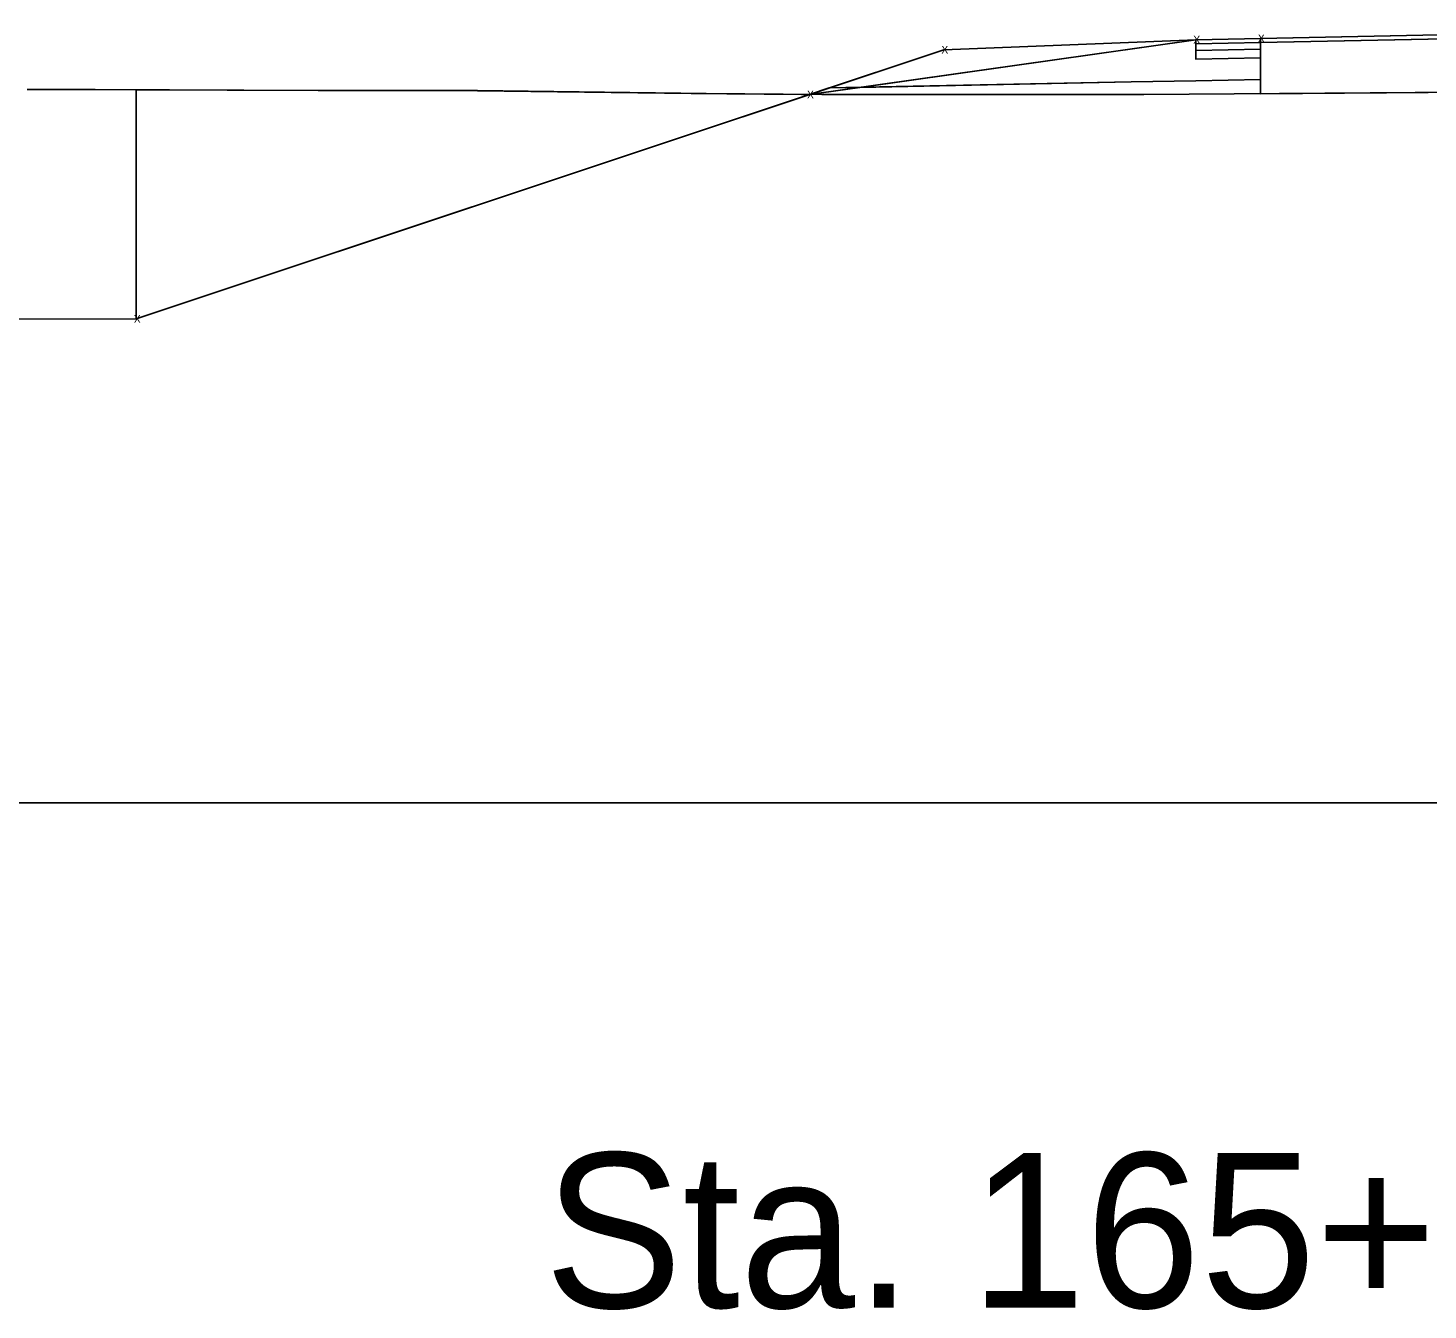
# Model space of a CAD drawing. Extents: x -26 to 303, y -16 to 6048.
# Drawn here: x 95.72 to 139.11, y 3984.28 to 4024.02 of the extents above; entities that cross this region are included whole.
import ezdxf

# ---------------------------------------------------------------- set-up
doc = ezdxf.new("R2010")
doc.units = 0
for name, color, linetype in [('ASPHALT_19MM1', 7, 'Continuous'), ('ASPHALT_9_5MM1', 7, 'Continuous'), ('CONST_DCH', 7, 'Continuous'), ('CONST_LV3', 7, 'Continuous'), ('Draft_XS_Text', 7, 'Continuous'), ('DTM_P_FINISHED_GRADE2', 7, 'Continuous'), ('DTM_TEMP_DROP', 7, 'Continuous'), ('DTM_X_GROUND', 7, 'Continuous'), ('TRANS_PAVED_SHOULDERS', 7, 'Continuous'), ('X_PROFILES_1', 7, 'Continuous'), ('XS_CELL', 7, 'Continuous'), ('XS_M_SHAPES_EARTHWORK', 7, 'Continuous'), ('XS_P_ASPHALT', 7, 'Continuous'), ('XS_P_GROUND', 7, 'Continuous'), ('XS_P_NULL_POINT', 7, 'Continuous'), ('XS_P_SHOULDER', 7, 'Continuous'), ('XS_P_SUBGRADE_GRANULAR', 7, 'Continuous'), ('XS_P_SUBGRADE_LEVELING', 7, 'Continuous'), ('XS_P_SUBGRADE_MILLING', 7, 'Continuous')]:
    doc.layers.add(name, color=color, linetype=linetype)

msp = doc.modelspace()

# ---------------------------------------------------------------- linework, layer by layer
at = {"layer": 'ASPHALT_19MM1'}
msp.add_lwpolyline([(133.91, 4023.365), (133.91, 4023.094), (131.91, 4023.054), (131.91, 4023.325), (133.91, 4023.365)], dxfattribs=at)
at = {"layer": 'ASPHALT_9_5MM1'}
msp.add_lwpolyline([(133.91, 4023.698), (133.91, 4023.573), (131.91, 4023.533), (131.91, 4023.658), (133.91, 4023.698)], dxfattribs=at)
at = {"layer": 'CONST_LV3'}
msp.add_lwpolyline([(150, 4024.02), (131.91, 4023.658)], dxfattribs=at)
at = {"layer": 'DTM_P_FINISHED_GRADE2'}
msp.add_lwpolyline([(119.938, 4021.957), (119.938, 4021.957), (124.103, 4023.346), (131.91, 4023.658), (133.91, 4023.698), (150, 4024.02), (166.254, 4023.695), (168.254, 4023.655), (176.244, 4023.335), (180.203, 4022.015)], dxfattribs=at)
at = {"layer": 'DTM_X_GROUND'}
for points in [[(95.689, 4022.111), (97.798, 4022.111), (104.708, 4022.08), (107.112, 4022.08), (109.407, 4022.08), (109.652, 4022.077), (116.269, 4021.99), (116.732, 4021.987), (117.374, 4021.982), (119.688, 4021.96), (119.938, 4021.957), (119.938, 4021.957), (131.91, 4023.658), (131.91, 4023.658), (133.91, 4023.698), (133.91, 4023.698), (150, 4024.02)], [(95.689, 4022.111), (97.798, 4022.111), (104.708, 4022.08), (107.112, 4022.08), (109.652, 4022.08), (116.732, 4021.989), (120.318, 4021.954), (124.862, 4021.956), (130.296, 4021.955), (144.322, 4022.065), (149.366, 4022.063), (154.591, 4022.06), (160.007, 4022.057), (168.822, 4021.928), (173.744, 4022.002), (177.71, 4022.001), (179.731, 4022.015), (185.132, 4022.015), (190.426, 4022.061), (194.742, 4022.061), (195.877, 4022.065), (200.356, 4022.064), (205.858, 4022.086)]]:
    msp.add_lwpolyline(points, dxfattribs=at)
at = {"layer": 'TRANS_PAVED_SHOULDERS'}
msp.add_lwpolyline([(133.91, 4023.573), (133.91, 4023.365), (131.91, 4023.325), (131.91, 4023.533), (133.91, 4023.573)], dxfattribs=at)
at = {"layer": 'XS_CELL'}
msp.add_line((0, 4000), (150, 4000), dxfattribs=at)
at = {"layer": 'XS_M_SHAPES_EARTHWORK'}
for points in [[(121.497, 4022.179), (131.91, 4023.658), (133.91, 4023.698), (150, 4024.02), (166.254, 4023.695), (168.254, 4023.655), (179.098, 4022.167), (170.213, 4022.345), (168.254, 4022.384), (166.254, 4022.424), (166.254, 4021.965), (160.007, 4022.057), (154.591, 4022.06), (150, 4022.062), (149.366, 4022.063), (144.322, 4022.065), (133.91, 4021.984), (133.91, 4022.427), (131.91, 4022.387), (129.91, 4022.347)], [(99.073, 4015.002), (99.073, 4022.105), (104.708, 4022.08), (107.112, 4022.08), (109.407, 4022.08), (109.652, 4022.077), (116.269, 4021.99), (116.732, 4021.987), (117.374, 4021.982), (119.688, 4021.96), (119.938, 4021.957)], [(119.938, 4021.957), (121.497, 4022.179), (120.545, 4022.16)]]:
    msp.add_lwpolyline(points, close=True, dxfattribs=at)
at = {"layer": 'XS_P_ASPHALT'}
msp.add_lwpolyline([(133.91, 4023.698), (133.91, 4023.573), (133.91, 4023.573), (150, 4023.895), (166.254, 4023.57), (166.254, 4023.57), (166.254, 4023.695), (166.254, 4023.695), (166.254, 4023.695), (150, 4024.02), (133.91, 4023.698), (133.91, 4023.698), (133.91, 4023.698)], dxfattribs=at)
at = {"layer": 'XS_P_GROUND'}
for points in [[(124.103, 4023.346), (99.073, 4015.002)], [(119.938, 4021.957), (119.938, 4021.957), (124.103, 4023.346)], [(95.215, 4014.998), (99.073, 4015.002)]]:
    msp.add_lwpolyline(points, dxfattribs=at)
at = {"layer": 'XS_P_SHOULDER'}
msp.add_lwpolyline([(131.91, 4023.658), (124.103, 4023.346)], dxfattribs=at)
msp.add_lwpolyline([(131.91, 4023.658), (124.103, 4023.346)], dxfattribs=at)
at = {"layer": 'XS_P_SUBGRADE_GRANULAR'}
for points in [[(133.91, 4022.427), (133.91, 4023.698)], [(131.91, 4022.387), (129.91, 4022.347), (120.545, 4022.16)], [(131.91, 4022.387), (129.91, 4022.347), (120.545, 4022.16)], [(131.91, 4022.387), (129.91, 4022.347), (120.545, 4022.16)], [(133.91, 4022.427), (131.91, 4022.387)]]:
    msp.add_lwpolyline(points, dxfattribs=at)
at = {"layer": 'XS_P_SUBGRADE_LEVELING'}
msp.add_lwpolyline([(144.322, 4023.781), (133.91, 4023.573), (133.91, 4023.573), (133.91, 4023.573), (133.91, 4023.573), (133.91, 4021.984), (133.91, 4021.984), (133.91, 4021.984), (144.322, 4022.065)], dxfattribs=at)
at = {"layer": 'XS_P_SUBGRADE_MILLING'}
msp.add_lwpolyline([(166.254, 4021.965), (166.254, 4021.965), (160.007, 4022.057), (160.007, 4022.057), (154.591, 4022.06), (154.591, 4022.06), (150, 4022.062), (149.366, 4022.063), (149.366, 4022.063), (144.322, 4022.065), (144.322, 4022.065), (133.91, 4021.984), (133.91, 4021.984), (133.91, 4021.984)], dxfattribs=at)
msp.add_lwpolyline([(166.254, 4021.965), (166.254, 4021.965), (160.007, 4022.057), (160.007, 4022.057), (154.591, 4022.06), (154.591, 4022.06), (150, 4022.062), (149.366, 4022.063), (149.366, 4022.063), (144.322, 4022.065), (144.322, 4022.065), (133.91, 4021.984), (133.91, 4021.984), (133.91, 4021.984)], dxfattribs=at)

# ---------------------------------------------------------------- texts
at = {"layer": 'CONST_DCH'}
msp.add_text('X', height=0.24, dxfattribs=at).set_placement((98.994, 4014.882))
at = {"layer": 'Draft_XS_Text'}
msp.add_text('Sta. 165+25.0000 R1', height=4.8, dxfattribs=at).set_placement((111.716, 3984.35))
at = {"layer": 'DTM_TEMP_DROP'}
for p in [(119.86, 4021.837), (98.994, 4014.882)]:
    msp.add_text('X', height=0.24, dxfattribs=at).set_placement(p)
at = {"layer": 'X_PROFILES_1'}
msp.add_text('X', height=0.24, dxfattribs=at).set_placement((124.024, 4023.226))
at = {"layer": 'XS_P_GROUND'}
msp.add_text('X', height=0.24, dxfattribs=at).set_placement((124.024, 4023.226))
at = {"layer": 'XS_P_NULL_POINT'}
for p in [(131.832, 4023.538), (133.832, 4023.578)]:
    msp.add_text('X', height=0.24, dxfattribs=at).set_placement(p)
at = {"layer": 'XS_P_SUBGRADE_GRANULAR'}
msp.add_text('X', height=0.24, dxfattribs=at).set_placement((119.86, 4021.837))

doc.saveas('drawing.dxf')
